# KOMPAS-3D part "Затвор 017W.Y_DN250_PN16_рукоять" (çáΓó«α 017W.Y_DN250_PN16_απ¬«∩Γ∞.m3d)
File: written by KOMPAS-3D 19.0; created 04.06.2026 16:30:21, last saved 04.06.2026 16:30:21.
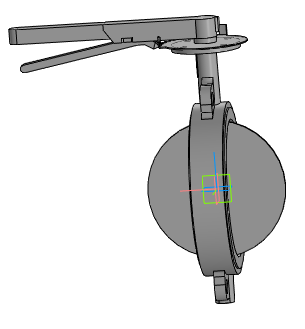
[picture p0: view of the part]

Document properties: Автор: Энергия; Полное имя файла: ..\..\..\3d для проектировщиков\017W разные\x.x Тип 017W.Y(S) Затвор дисковый поворотный межфланцевый\Затвор 017W.Y(S)_DN32-DN350_рукоять\Затвор 017W.Y_DN250_PN16_рукоять.a3d

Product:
- Part/product: Затвор 017W.Y_DN250_PN16_рукоять
    Масса: 24.5212

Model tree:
1. Операция без истории:1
